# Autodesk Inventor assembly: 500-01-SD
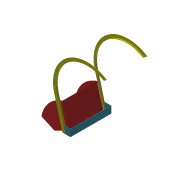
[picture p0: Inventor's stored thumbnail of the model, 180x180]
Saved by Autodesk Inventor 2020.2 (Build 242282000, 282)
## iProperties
Created: 2014-10
Part Number: 500-01-SD
Document SubType Name: Assembly
Designer: F.Stasiak
Catalog Web Link: www.expertbooks.pl
Manager: www.cadconsulting.pl
Company: Fabian Stasiak CAD Consulting
Author: F.Stasiak
Subject: Zbiór ćwiczeń. Autodesk Inventor 2020. Kurs Professional
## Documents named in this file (6)
- C:\2020_Kurs_Professional\R3 Dynamika\500-01-SD.iam
- C:\2020_Kurs_Professional\R3 Dynamika\Komponenty_dyn\Szyna_500_01.ipt
- C:\2020_Kurs_Professional\R3 Dynamika\Komponenty_dyn\Szyna_500_02.ipt
- C:\2020_Kurs_Professional\R3 Dynamika\Komponenty_dyn\Łycha_500_01.ipt
- C:\2020_Kurs_Professional\R3 Dynamika\Komponenty_dyn\Kółko_500.ipt
- C:\2020_Kurs_Professional\R3 Dynamika\Komponenty_dyn\Baza_500.ipt
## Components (8 placed, 5 different names)
1. Baza_500:1 — Równoległy:11, Równoległy:12, Równoległy:13, Równoległy:14, Równoległy:15, Zestawiający:16, Zestawiający:17
2. Szyna_500_01:1 — Przejściowy:1, Przejściowy:2, Równoległy:12, Równoległy:13, Zestawiający:16
3. Szyna_500_02:1 — Równoległy:14, Równoległy:15, Zestawiający:17
4. Łycha_500_01:1 — PODNIESIENIE, Wstaw:1, Wstaw:2, Wstaw:3, Wstaw:4, Równoległy:11
5. Kółko_500:1 — Wstaw:1, Przejściowy:2
6. Kółko_500:2 — Wstaw:2, Przejściowy:1
7. Kółko_500:3 — Wstaw:3
8. Kółko_500:4 — Wstaw:4
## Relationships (14: Flush 5, Insert 4, Mate 3, Transitional 2)
- PODNIESIENIE [Mate]: Łycha_500_01:1
- Wstaw:1 [Insert]: Łycha_500_01:1 ↔ Kółko_500:1
- Wstaw:2 [Insert]: Łycha_500_01:1 ↔ Kółko_500:2
- Wstaw:3 [Insert]: Łycha_500_01:1 ↔ Kółko_500:3
- Wstaw:4 [Insert]: Łycha_500_01:1 ↔ Kółko_500:4
- Równoległy:11 [Flush]: Baza_500:1 ↔ Łycha_500_01:1
- Przejściowy:1 [Transitional]: Szyna_500_01:1 ↔ Kółko_500:2
- Przejściowy:2 [Transitional]: Szyna_500_01:1 ↔ Kółko_500:1
- Równoległy:12 [Flush]: Baza_500:1 ↔ Szyna_500_01:1
- Równoległy:13 [Flush]: Baza_500:1 ↔ Szyna_500_01:1
- Równoległy:14 [Flush]: Baza_500:1 ↔ Szyna_500_02:1
- Równoległy:15 [Flush]: Baza_500:1 ↔ Szyna_500_02:1
- Zestawiający:16 [Mate]: Baza_500:1 ↔ Szyna_500_01:1
- Zestawiający:17 [Mate]: Baza_500:1 ↔ Szyna_500_02:1
